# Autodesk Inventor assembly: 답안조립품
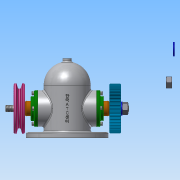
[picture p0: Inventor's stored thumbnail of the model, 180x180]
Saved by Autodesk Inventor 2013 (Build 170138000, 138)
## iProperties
Created: 2019-11
Part Number: 답안조립품
Document SubType Name: Assembly
Designer: Administrator
Author: Administrator
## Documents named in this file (14)
- C:\Users\Administrator\Documents\Inventor\491104V1044\답안조립품.iam
- C:\Users\Administrator\Documents\Inventor\491104V1044\본체.ipt
- C:\Users\Administrator\Documents\Inventor\491104V1044\V-벨트풀리.ipt
- V-벨트풀리.ipt
- C:\Users\Administrator\Documents\Inventor\491104V1044\너트 M12x1.25.ipt
- C:\Users\Administrator\Documents\Inventor\491104V1044\베어링 6203.ipt
- C:\Users\Administrator\Documents\Inventor\491104V1044\볼트 M4.ipt
- C:\Users\Administrator\Documents\Inventor\491104V1044\부시.ipt
- C:\Users\Administrator\Documents\Inventor\491104V1044\스퍼기어.ipt
- C:\Users\Administrator\Documents\Inventor\491104V1044\오일 실 26 38 8.ipt
- C:\Users\Administrator\Documents\Inventor\491104V1044\와셔 12x24.ipt
- C:\Users\Administrator\Documents\Inventor\491104V1044\축.ipt
- C:\Users\Administrator\Documents\Inventor\491104V1044\커버.ipt
- C:\Users\Administrator\Documents\Inventor\491104V1044\키 5x5x12.ipt
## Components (1 placed, 1 different names)
1. V-벨트풀리:1
